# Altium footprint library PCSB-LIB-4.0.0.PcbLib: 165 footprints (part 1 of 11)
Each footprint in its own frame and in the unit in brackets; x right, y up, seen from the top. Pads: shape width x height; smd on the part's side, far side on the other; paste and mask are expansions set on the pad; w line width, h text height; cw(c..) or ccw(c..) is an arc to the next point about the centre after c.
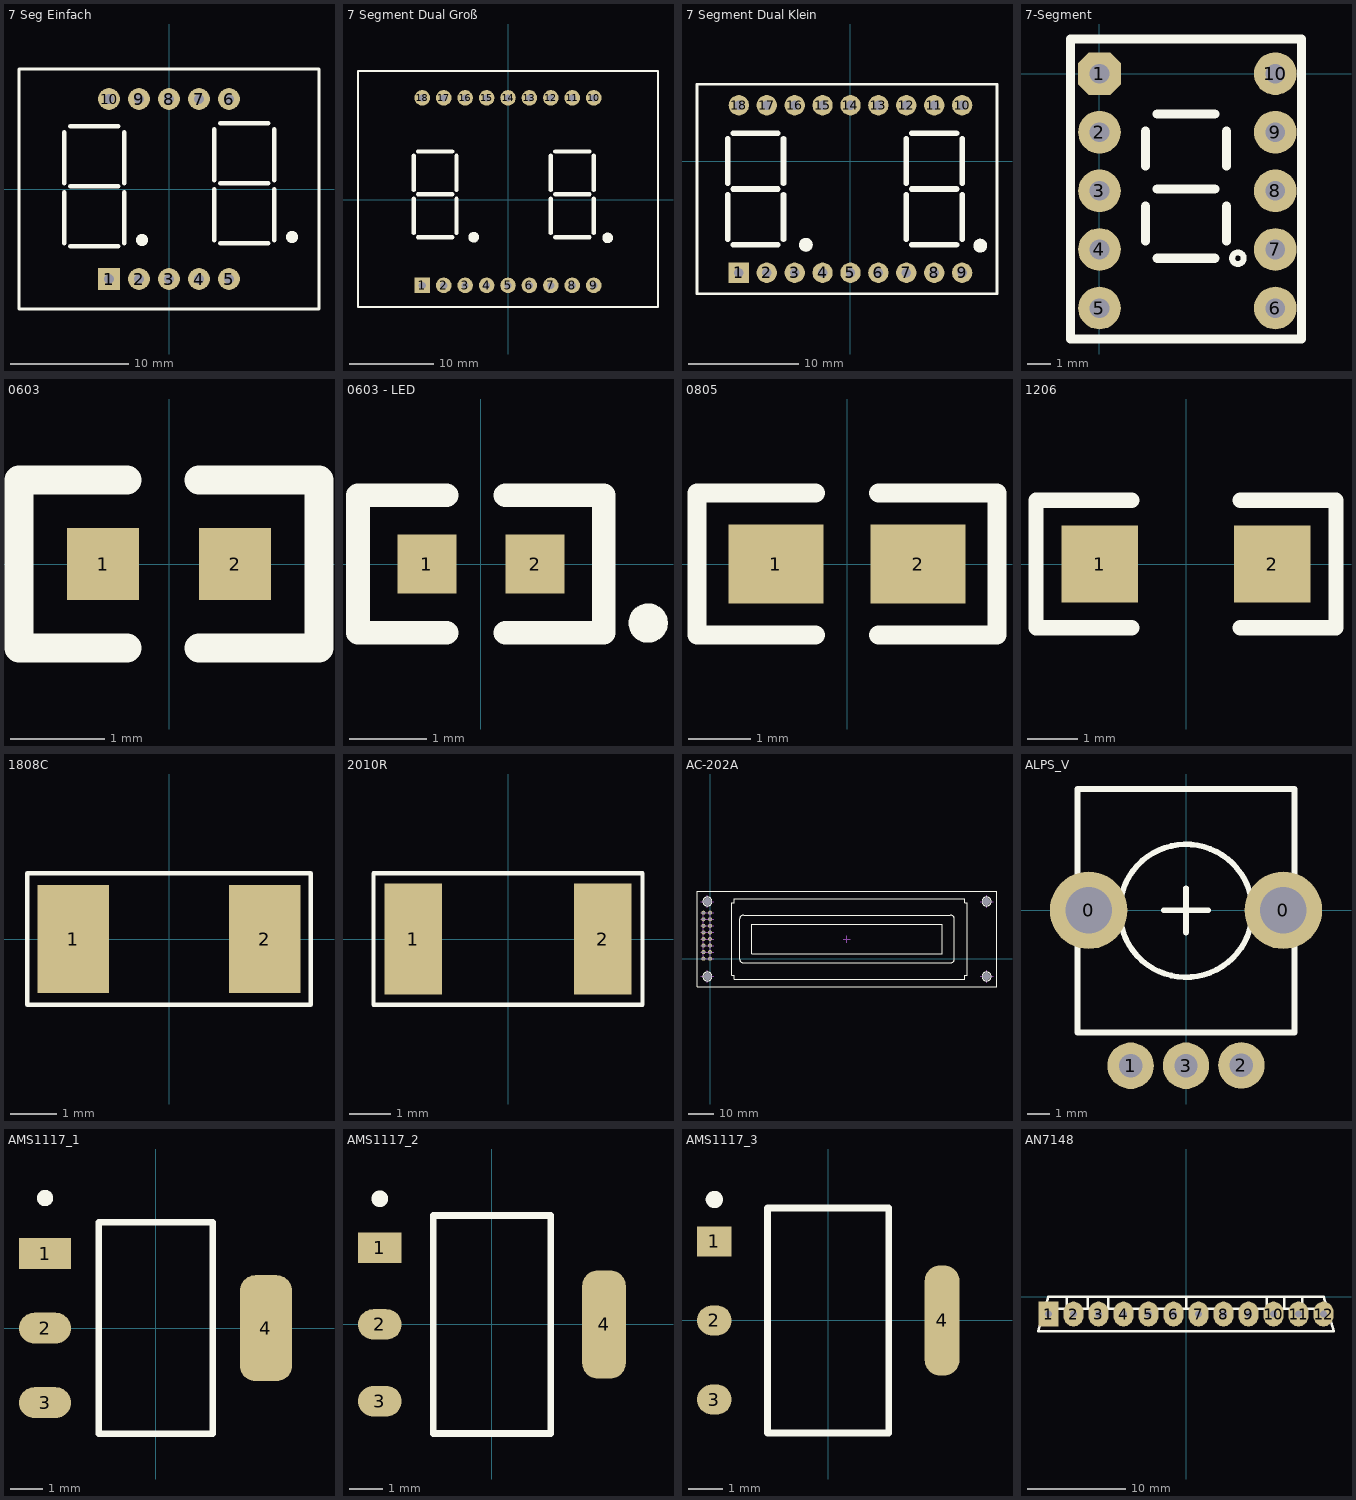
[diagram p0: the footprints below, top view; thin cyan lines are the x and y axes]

## 7 Seg Einfach [mm]
pads (10):
  rect 1.85x1.85 hole 0.85: 1(-5.08,-7.62)
  round 1.85 hole 0.85: 2(-2.54,-7.62) 3(0,-7.62) 4(2.54,-7.62) 5(5.08,-7.62) 6(5.08,7.62) 7(2.54,7.62) 8(0,7.62) 9(-2.54,7.62) 10(-5.08,7.62)
Top Overlay:
  circle w0.508: c10.414,-4.064 r0.254
  circle w0.508: c-2.286,-4.318 r0.254
  lines w0.254: 0,10.16 12.7,10.16 ; 12.7,10.16 12.7,-10.16 -12.7,-10.16 -12.7,10.16 12.7,10.16
  lines w0.381: -8.89,-4.572 -8.89,-0.254 ; -8.89,0.508 -8.89,4.826 ; -8.382,-4.826 -4.318,-4.826 ; -8.382,0.254 -4.318,0.254 ; -8.382,5.334 -4.318,5.334 ; -3.81,-4.572 -3.81,-0.254 ; -3.81,0.508 -3.81,4.826 ; 3.81,-4.318 3.81,0 ; 3.81,0.762 3.81,5.08 ; 4.318,-4.572 8.382,-4.572 ; 4.318,0.508 8.382,0.508 ; 4.318,5.588 8.382,5.588 ; 8.89,-4.318 8.89,0 ; 8.89,0.762 8.89,5.08

## 7 Segment Dual Groß [mm]
pads (18):
  rect 1.85x1.85 hole 0.85: 1(-10.16,-10.16)
  round 1.85 hole 0.85: 2(-7.62,-10.16) 3(-5.08,-10.16) 4(-2.54,-10.16) 5(0,-10.16) 6(2.54,-10.16) 7(5.08,-10.16) 8(7.62,-10.16) 9(10.16,-10.16) 10(10.16,12.065) 11(7.62,12.065) 12(5.08,12.065) 13(2.54,12.065) 14(0,12.065) 15(-2.54,12.065) 16(-5.08,12.065) 17(-7.62,12.065) 18(-10.16,12.065)
Top Overlay:
  circle w0.254: c-4.064,-4.445 r0.508
  circle w0.254: c11.811,-4.521 r0.508
  rectangle: -4.47,-4.851 -3.607,-4.013
  rectangle: 11.405,-4.928 12.217,-4.064
  lines w0.254: -17.78,-12.7 -17.78,15.24 17.78,15.24 17.78,-12.7 -17.78,-12.7
  lines w0.508: -11.176,-3.937 -11.176,0.127 ; -11.176,1.143 -11.176,5.207 ; -10.668,-4.445 -6.604,-4.445 ; -10.668,0.635 -6.604,0.635 ; -10.668,5.715 -6.604,5.715 ; -6.096,-3.937 -6.096,0.127 ; -6.096,1.143 -6.096,5.207 ; 5.08,-3.937 5.08,0.127 ; 5.08,1.143 5.08,5.207 ; 5.588,-4.445 9.652,-4.445 ; 5.588,0.635 9.652,0.635 ; 5.588,5.715 9.652,5.715 ; 10.16,-3.937 10.16,0.127 ; 10.16,1.143 10.16,5.207

## 7 Segment Dual Klein [mm]
pads (18):
  rect 1.85x1.85 hole 0.85: 1(-10.16,-10.16)
  round 1.85 hole 0.85: 2(-7.62,-10.16) 3(-5.08,-10.16) 4(-2.54,-10.16) 5(0,-10.16) 6(2.54,-10.16) 7(5.08,-10.16) 8(7.62,-10.16) 9(10.16,-10.16) 10(10.16,5.08) 11(7.62,5.08) 12(5.08,5.08) 13(2.54,5.08) 14(0,5.08) 15(-2.54,5.08) 16(-5.08,5.08) 17(-7.62,5.08) 18(-10.16,5.08)
Top Overlay:
  circle w0.254: c11.811,-7.696 r0.508
  circle w0.254: c-4.064,-7.62 r0.508
  rectangle: 11.405,-8.103 12.217,-7.239
  rectangle: -4.47,-8.026 -3.607,-7.188
  lines w0.254: -13.97,-12.065 13.335,-12.065 13.335,6.985 -13.97,6.985 -13.97,-12.065
  lines w0.508: -11.176,-7.112 -11.176,-3.048 ; -11.176,-2.032 -11.176,2.032 ; -10.668,-7.62 -6.604,-7.62 ; -10.668,-2.54 -6.604,-2.54 ; -10.668,2.54 -6.604,2.54 ; -6.096,-7.112 -6.096,-3.048 ; -6.096,-2.032 -6.096,2.032 ; 5.08,-7.112 5.08,-3.048 ; 5.08,-2.032 5.08,2.032 ; 5.588,-7.62 9.652,-7.62 ; 5.588,-2.54 9.652,-2.54 ; 5.588,2.54 9.652,2.54 ; 10.16,-7.112 10.16,-3.048 ; 10.16,-2.032 10.16,2.032

## 7-Segment [mm]
pads (10):
  oct 1.85x1.85 hole 0.85: 1(0,0)
  round 1.85 hole 0.85: 2(0,-2.54) 3(0,-5.08) 4(0,-7.62) 5(0,-10.16) 6(7.62,-10.16) 7(7.62,-7.62) 8(7.62,-5.08) 9(7.62,-2.54) 10(7.62,0)
Top Overlay:
  circle w0.254: c6,-8 r0.25
  lines w0.4: 2,-7.25 2,-5.75 ; 2,-4 2,-2.5 ; 2.5,-8 5,-8 ; 2.5,-5 5,-5 ; 2.5,-1.75 5,-1.75 ; 5.5,-7.25 5.5,-5.75 ; 5.5,-4 5.5,-2.5 ; -1.25,-11.5 8.75,-11.5 8.75,1.5 -1.25,1.5 -1.25,-11.5

## 0603 [mil]
pads (2):
  rect 30x30 smd: 1(-27.5,0) 2(27.5,0)
Top Overlay:
  lines w12: -17.5,-35 -62.5,-35 -62.5,35 -17.5,35 ; 12.5,-35 62.5,-35 62.5,35 12.5,35

## 0603 - LED [mil]
pads (2):
  rect 30x30 smd: 1(-27.5,0) 2(27.5,0)
Top Overlay:
  circle w10: c85,-30 r5
  lines w12: -17.5,-35 -62.5,-35 -62.5,35 -17.5,35 ; 12.5,-35 62.5,-35 62.5,35 12.5,35

## 0805 [mil]
pads (2):
  rect 60x50 smd: 1(-45,0) 2(45,0)
Top Overlay:
  lines w12: -20,-45 -95,-45 -95,45 -20,45 ; 20,-45 95,-45 95,45 20,45

## 1206 [mil]
pads (2):
  rect 60x60 smd: 1(-67.5,0) 2(67.5,0)
Top Overlay:
  lines w12: -42.5,-50 -117.5,-50 -117.5,50 -42.5,50 ; 42.5,-50 117.5,-50 117.5,50 42.5,50

## 1808C [mm] "Chip Capacitor, 2-Leads, Body 4,5x2,0mm, IPC Medium Density"
height 2
pads (2):
  rect 1.55x2.35 smd: 1(-2.075,0) 2(2.075,0)
Top Overlay:
  lines w0.1: -3.075,-1.425 -3.075,1.425 3.075,1.425 3.075,-1.425 -3.075,-1.425

## 2010R [mm] "Chip Resistor, 2-Leads, Body 5.0x2.5mm, IPC Medium Density"
height 0.7
pads (2):
  rect 1.4x2.7 smd: 1(-2.3,0) 2(2.3,0)
Top Overlay:
  lines w0.1: -3.275,-1.6 -3.275,1.6 3.275,1.6 3.275,-1.6 -3.275,-1.6

## AC-202A [mm]
pads (20):
  round 0 hole 3.15: 0(-1.041,-6.883) 0(-1.041,22.123) 0(106.959,-6.883) 0(106.959,22.123)
  round 1.55 hole 1: 1(0,0) 2(-2.54,0) 3(0,2.54) 4(-2.54,2.54) 5(0,5.08) 6(-2.54,5.08) 7(0,7.62) 8(-2.54,7.62) 9(0,10.16) 10(-2.54,10.16) 11(0,12.7) 12(-2.54,12.7) 13(0,15.24) 14(-2.54,15.24) 15(0,17.78) 16(-2.54,17.78)
Top Overlay:
  circle w0.051: c-1.031,22.113 r1.75
  circle w0.051: c106.969,22.113 r1.75
  circle w0.051: c106.969,-6.887 r1.75
  circle w0.051: c-1.031,-6.887 r1.75
  lines w0.254: -5.031,-10.887 110.969,-10.887 ; -5.031,-10.887 -5.031,26.113 ; -5.031,-10.887 -5.031,26.113 ; -5.031,26.113 110.969,26.113 ; -5.031,26.113 110.969,26.113 ; 110.969,-10.887 110.969,26.113 ; 110.969,-10.887 110.969,26.113 ; 8.369,-6.487 8.369,21.713 9.369,21.713 9.369,23.213 98.569,23.213 98.569,21.713 99.569,21.713 99.569,-6.487 98.569,-6.487 98.569,-7.987 9.369,-7.987 9.369,-6.487 8.369,-6.487 ; 11.469,-0.137 ccw(c12.969,-0.137) 12.969,-1.637 92.969,-1.637 ccw(c92.969,-0.137) 94.469,-0.137 94.469,15.363 ccw(c92.969,15.363) 92.969,16.863 12.969,16.863 ccw(c12.969,15.363) 11.469,15.363 11.469,-0.137 ; 16.219,1.863 89.719,1.863 89.719,13.363 16.219,13.363 16.219,1.863
Mechanical 1:
  circle w0.025: c110.969,-10.887 r0.013
  circle w0.025: c-5.031,-10.887 r0.013
  circle w0.025: c110.969,-10.887 r0.013
  circle w0.025: c110.969,26.113 r0.013
  lines w0.051: -3.531,-6.887 1.469,-6.887 ; -3.531,-0.007 1.469,-0.007 ; -3.531,2.533 1.469,2.533 ; -3.531,5.073 1.469,5.073 ; -3.531,7.613 1.469,7.613 ; -3.531,10.153 1.469,10.153 ; -3.531,12.693 1.469,12.693 ; -3.531,15.233 1.469,15.233 ; -3.531,17.773 1.469,17.773 ; -3.531,22.113 1.469,22.113 ; -2.531,-0.007 -2.531,17.773 ; -1.031,-9.387 -1.031,-4.387 ; -1.031,19.613 -1.031,24.613 ; 0.009,-0.007 0.009,17.773 ; 51.537,7.544 54.305,7.518 ; 52.959,6.172 52.959,8.941 ; 104.469,-6.887 109.469,-6.887 ; 104.469,22.113 109.469,22.113 ; 106.969,-9.387 106.969,-4.387 ; 106.969,19.613 106.969,24.613

## ALPS_V [mm]
height 15
pads (5):
  round 3.5 hole 2.1: 0(-4.4,0) 0(4.4,0)
  round 2.1 hole 1.05: 1(-2.5,-7.02) 2(2.5,-7) 3(0,-7.02)
Top Overlay:
  circle w0.254: c0,-0.02 r3
  lines w0.254: -1,0 1,0 ; 0,-1 0,0 0,1 ; -4.9,-5.52 4.9,-5.52 4.9,5.48 -4.9,5.48 -4.9,-5.52

## AMS1117_1 [mm]
pads (4):
  rect 1.604x0.952 smd paste+0 mask+0: 1(-3.395,2.29)
  rrect100% 1.604x0.952 smd paste+0 mask+0: 2(-3.395,0) 3(-3.395,-2.29)
  rrect59% 1.604x3.262 smd paste+0 mask+0: 4(3.395,0)
Top Overlay:
  circle w0.25: c-3.395,4 r0.125
  lines w0.2: -1.753,-3.253 -1.753,3.253 1.753,3.253 1.753,-3.253 -1.753,-3.253
Mechanical 5:

## AMS1117_2 [mm]
pads (4):
  rect 1.304x0.912 smd paste+0 mask+0: 1(-3.345,2.29)
  rrect100% 1.304x0.912 smd paste+0 mask+0: 2(-3.345,0) 3(-3.345,-2.29)
  rrect70% 1.304x3.222 smd paste+0 mask+0: 4(3.345,0)
Top Overlay:
  circle w0.25: c-3.345,3.75 r0.125
  lines w0.2: -1.753,-3.253 1.753,-3.253 1.753,3.253 -1.753,3.253 -1.753,-3.253

## AMS1117_3 [mm]
pads (4):
  rect 1.004x0.872 smd paste+0 mask+0: 1(-3.295,2.29)
  rrect100% 1.004x0.872 smd paste+0 mask+0: 2(-3.295,0) 3(-3.295,-2.29)
  rrect87% 1.004x3.182 smd paste+0 mask+0: 4(3.295,0)
Top Overlay:
  circle w0.25: c-3.295,3.5 r0.125
  lines w0.2: -1.753,-3.253 1.753,-3.253 1.753,3.253 -1.753,3.253 -1.753,-3.253

## AN7148 [mm]
pads (12):
  rect 2x2.54 hole 0.75: 1(-13.97,-1.753)
  oval 2x2.54 hole 0.75: 2(-11.43,-1.753) 3(-8.89,-1.753) 4(-6.35,-1.753) 5(-3.81,-1.753) 6(-1.27,-1.753) 7(1.27,-1.753) 8(3.81,-1.753) 9(6.35,-1.753) 10(8.89,-1.753) 11(11.43,-1.753) 12(13.97,-1.753)
Top Overlay:
  lines w0.254: -14.343,-1.2 14.343,-1.2 ; -12.1,-1.2 -12.1,0 ; -10,-1.2 -10,0 ; -7.9,-1.2 -7.9,0 ; 0,-1.2 0,0 ; 8.2,-1.2 8.2,0 ; 10,-1.2 10,0 ; 11.8,-1.2 11.8,0 ; -15,-3.5 15,-3.5 14,0 -14,0 -15,-3.5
